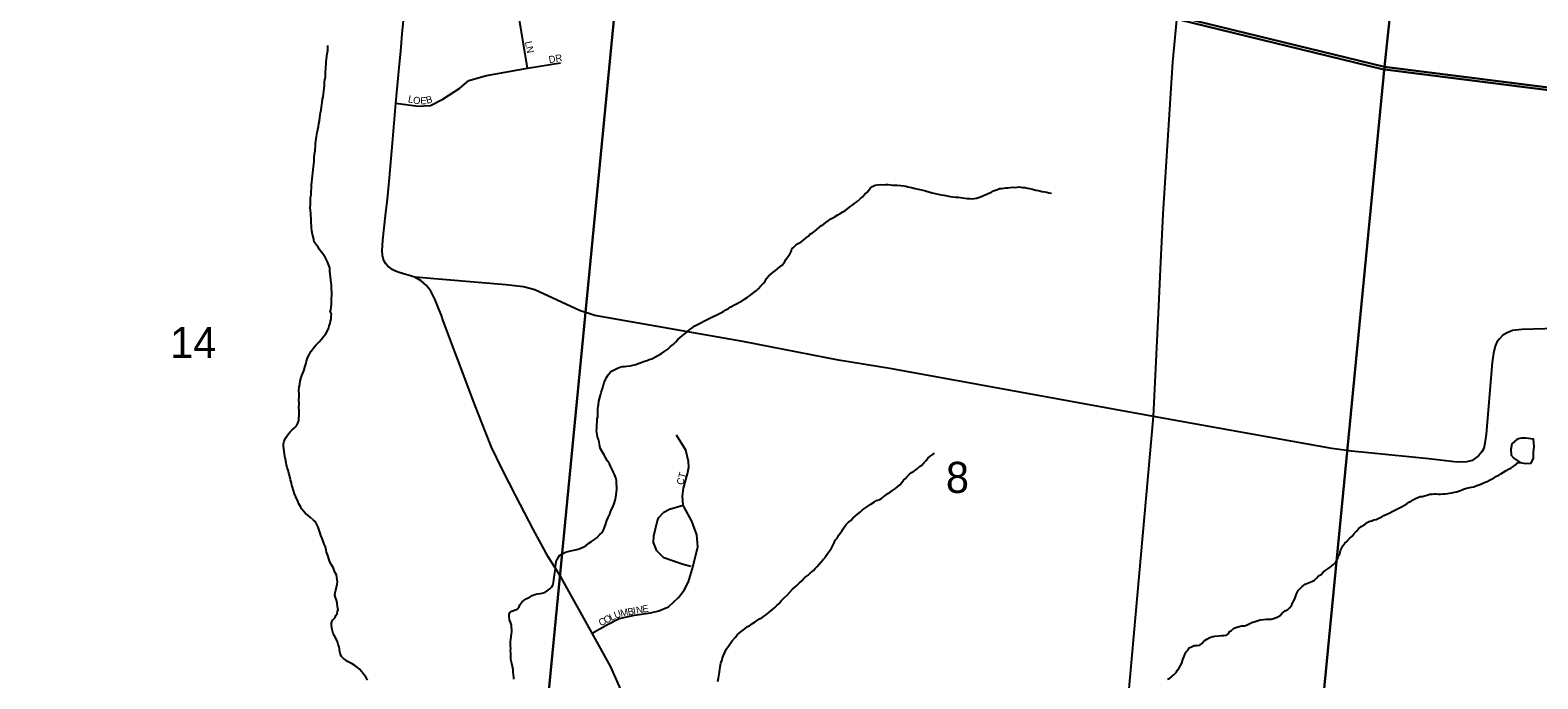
# Model space of a CAD drawing. Extents: x 0 to 1064, y 0 to 440.
# Drawn here: x 203.09 to 235.6, y 278.69 to 292.66 of the extents above; entities that cross this region are included whole.
import ezdxf

# ---------------------------------------------------------------- set-up
doc = ezdxf.new("R2010")
doc.units = 0
for name, color, linetype in [('GM_X_County_Road', 7, 'Continuous'), ('GM_X_Minor_Lake', 7, 'Continuous'), ('GM_X_Minor_River', 7, 'Continuous'), ('GM_X_Section', 7, 'Continuous'), ('GM_X_Section_Text', 7, 'Continuous'), ('GM_X_State_Route', 7, 'Continuous'), ('GM_X_Township', 7, 'Continuous'), ('GM_X_Township_Road', 7, 'Continuous'), ('GM_X_Township_Subdivision', 7, 'Continuous'), ('GM_X_Township_Subdivision_Text', 7, 'Continuous')]:
    doc.layers.add(name, color=color, linetype=linetype)

msp = doc.modelspace()

# ---------------------------------------------------------------- linework, layer by layer
at = {"layer": 'GM_X_County_Road'}
msp.add_lwpolyline([(227.217, 256.331), (227.021, 256.544), (226.463, 257.231), (226.198, 257.65), (225.438, 259.12), (225.221, 259.508), (225.122, 259.711), (225.097, 259.973), (225.685, 266.061), (225.937, 268.726), (226.312, 273.171), (227.313, 284.338), (227.421, 286.562), (227.469, 287.662), (227.522, 288.708), (227.683, 291.298), (227.726, 291.973), (227.812, 292.884)], dxfattribs=at)
at = {"layer": 'GM_X_Minor_Lake'}
for points in [[(235.24, 283.872), (235.154, 283.849), (235.042, 283.749), (235.015, 283.628), (235.024, 283.506), (235.083, 283.437), (235.221, 283.349)], [(235.221, 283.349), (235.33, 283.328), (235.458, 283.331), (235.503, 283.439), (235.506, 283.567), (235.522, 283.694), (235.507, 283.853), (235.337, 283.869), (235.24, 283.872)]]:
    msp.add_lwpolyline(points, dxfattribs=at)
at = {"layer": 'GM_X_Minor_River'}
for points in [[(209.589, 286.828), (209.591, 286.876), (209.594, 286.955), (209.595, 287.01), (209.592, 287.089), (209.588, 287.162), (209.578, 287.235), (209.574, 287.278), (209.564, 287.357), (209.559, 287.399), (209.556, 287.478), (209.552, 287.539), (209.524, 287.613), (209.502, 287.674), (209.462, 287.755), (209.433, 287.798), (209.404, 287.841), (209.368, 287.885), (209.328, 287.935), (209.299, 287.984), (209.264, 288.028), (209.217, 288.102), (209.207, 288.145), (209.191, 288.218), (209.18, 288.261), (209.164, 288.34), (209.161, 288.413), (209.156, 288.456), (209.152, 288.511), (209.147, 288.56), (209.149, 288.614), (209.145, 288.669), (209.14, 288.718), (209.136, 288.778), (209.132, 288.839), (209.134, 288.906), (209.136, 288.954), (209.137, 289.003), (209.139, 289.058), (209.147, 289.118), (209.15, 289.185), (209.158, 289.257), (209.16, 289.324), (209.162, 289.391), (209.171, 289.457), (209.179, 289.518), (209.187, 289.59), (209.19, 289.663), (209.198, 289.717), (209.206, 289.778), (209.214, 289.838), (209.216, 289.917), (209.225, 289.996), (209.233, 290.062), (209.235, 290.105), (209.242, 290.147), (209.245, 290.22), (209.252, 290.268), (209.268, 290.371), (209.283, 290.455), (209.297, 290.522), (209.306, 290.588), (209.314, 290.649), (209.328, 290.703), (209.336, 290.782), (209.344, 290.842), (209.352, 290.884), (209.366, 290.945), (209.374, 291.011), (209.382, 291.053), (209.39, 291.114), (209.398, 291.174), (209.406, 291.223), (209.414, 291.289), (209.422, 291.35), (209.43, 291.41), (209.438, 291.464), (209.441, 291.543), (209.448, 291.598), (209.456, 291.64), (209.457, 291.682), (209.459, 291.731), (209.461, 291.779), (209.468, 291.822), (209.47, 291.87), (209.472, 291.931), (209.473, 291.979), (209.481, 292.04), (209.49, 292.106), (209.497, 292.155), (209.506, 292.227), (209.508, 292.282), (209.509, 292.336)], [(219.515, 287.948), (219.559, 287.989), (219.602, 288.03), (219.652, 288.065), (219.708, 288.094), (219.771, 288.147), (219.821, 288.188), (219.871, 288.223), (219.902, 288.264), (219.958, 288.299), (220.002, 288.328), (220.058, 288.375), (220.108, 288.416), (220.152, 288.457), (220.202, 288.485), (220.246, 288.521), (220.296, 288.555), (220.352, 288.596), (220.395, 288.619), (220.445, 288.648), (220.507, 288.682), (220.557, 288.711), (220.613, 288.746), (220.675, 288.787), (220.725, 288.821), (220.787, 288.868), (220.831, 288.897), (220.874, 288.932), (220.918, 288.967), (220.987, 289.026), (221.037, 289.073), (221.088, 289.126), (221.132, 289.167), (221.176, 289.214), (221.208, 289.262), (221.252, 289.297), (221.308, 289.326), (221.362, 289.33), (221.417, 289.334), (221.49, 289.332), (221.533, 289.337), (221.594, 289.335), (221.642, 289.327), (221.685, 289.326), (221.74, 289.324), (221.788, 289.323), (221.861, 289.315), (221.928, 289.306), (221.97, 289.299), (222.012, 289.286), (222.097, 289.271), (222.176, 289.25), (222.236, 289.236), (222.309, 289.222), (222.393, 289.201), (222.466, 289.181), (222.538, 289.16), (222.604, 289.14), (222.671, 289.126), (222.732, 289.118), (222.792, 289.104), (222.865, 289.095), (222.925, 289.081), (222.986, 289.073), (223.046, 289.065), (223.101, 289.064), (223.15, 289.056), (223.192, 289.049), (223.247, 289.041), (223.295, 289.034), (223.35, 289.032), (223.404, 289.03), (223.447, 289.035), (223.496, 289.046), (223.558, 289.062), (223.619, 289.084), (223.663, 289.107), (223.718, 289.13), (223.762, 289.153), (223.817, 289.175), (223.861, 289.198), (223.904, 289.215), (223.947, 289.232), (223.99, 289.249), (224.039, 289.253), (224.125, 289.269), (224.173, 289.267), (224.222, 289.272), (224.265, 289.277), (224.326, 289.275), (224.375, 289.279), (224.424, 289.284), (224.484, 289.276), (224.539, 289.274), (224.593, 289.261), (224.636, 289.253), (224.702, 289.239), (224.774, 289.213), (224.823, 289.205), (224.865, 289.198), (224.908, 289.19)], [(224.908, 289.19), (224.968, 289.182), (225.011, 289.175), (225.053, 289.161), (225.113, 289.147)], [(215.374, 283.693), (215.369, 283.742), (215.358, 283.784), (215.348, 283.839), (215.326, 283.901), (215.315, 283.95), (215.31, 283.992), (215.3, 284.035), (215.313, 284.083), (215.31, 284.162), (215.318, 284.217), (215.32, 284.29), (215.328, 284.332), (215.33, 284.392), (215.331, 284.435), (215.334, 284.508), (215.341, 284.55), (215.342, 284.592), (215.351, 284.665), (215.365, 284.719), (215.386, 284.797), (215.406, 284.858), (215.433, 284.942), (215.454, 285.014), (215.468, 285.068), (215.494, 285.134), (215.52, 285.182), (215.552, 285.235), (215.597, 285.289), (215.641, 285.324), (215.709, 285.358), (215.752, 285.381), (215.807, 285.398), (215.857, 285.414), (215.906, 285.419), (215.954, 285.423), (216.028, 285.433), (216.083, 285.444), (216.15, 285.46), (216.2, 285.483), (216.262, 285.505), (216.317, 285.521), (216.397, 285.543), (216.44, 285.566), (216.496, 285.583), (216.576, 285.623), (216.638, 285.657), (216.706, 285.698), (216.775, 285.744), (216.837, 285.791), (216.9, 285.843), (216.956, 285.89), (217.007, 285.943), (217.057, 285.996), (217.107, 286.037), (217.157, 286.084), (217.214, 286.125), (217.258, 286.166), (217.314, 286.213), (217.358, 286.242), (217.42, 286.289), (217.482, 286.317), (217.538, 286.346), (217.618, 286.392), (217.686, 286.426), (217.748, 286.455), (217.804, 286.489), (217.884, 286.523), (217.928, 286.546), (217.983, 286.575), (218.046, 286.609), (218.089, 286.638), (218.145, 286.667), (218.201, 286.702), (218.263, 286.736), (218.319, 286.765), (218.387, 286.799), (218.443, 286.834), (218.492, 286.869), (218.548, 286.903), (218.63, 286.962), (218.698, 287.008), (218.754, 287.055), (218.792, 287.096), (218.849, 287.155), (218.906, 287.214), (218.938, 287.256), (218.97, 287.309), (219.014, 287.363), (219.058, 287.404), (219.108, 287.439), (219.164, 287.485), (219.208, 287.521), (219.252, 287.562), (219.308, 287.596), (219.353, 287.662), (219.392, 287.727), (219.424, 287.775), (219.468, 287.834), (219.507, 287.906), (219.515, 287.948)], [(209.631, 281.072), (209.59, 281.14), (209.556, 281.207), (209.534, 281.269), (209.512, 281.342), (209.484, 281.416), (209.473, 281.459), (209.457, 281.526), (209.428, 281.588), (209.406, 281.655), (209.384, 281.711), (209.361, 281.772), (209.345, 281.821), (209.328, 281.864), (209.317, 281.907), (209.3, 281.95), (209.272, 282.011), (209.243, 282.067), (209.202, 282.105), (209.137, 282.161), (209.078, 282.212), (209.03, 282.25), (208.983, 282.3), (208.948, 282.343), (208.925, 282.386), (208.885, 282.454), (208.862, 282.516), (208.823, 282.608), (208.794, 282.67), (208.772, 282.743), (208.751, 282.817), (208.734, 282.86), (208.723, 282.903), (208.707, 282.97), (208.691, 283.043), (208.669, 283.117), (208.653, 283.184), (208.636, 283.233), (208.62, 283.3), (208.61, 283.343), (208.594, 283.417), (208.584, 283.478), (208.573, 283.532), (208.569, 283.587), (208.559, 283.648), (208.554, 283.697), (208.556, 283.746), (208.57, 283.806), (208.597, 283.872), (208.622, 283.913), (208.661, 283.967), (208.699, 284.008), (208.743, 284.049), (208.786, 284.084), (208.837, 284.137), (208.863, 284.191), (208.883, 284.251), (208.885, 284.3), (208.893, 284.354), (208.888, 284.403), (208.891, 284.476), (208.886, 284.531), (208.889, 284.609), (208.886, 284.707), (208.888, 284.755), (208.89, 284.822), (208.886, 284.895), (208.889, 284.968), (208.903, 285.034), (208.911, 285.1), (208.932, 285.179), (208.952, 285.221), (208.972, 285.269), (208.992, 285.323), (209.005, 285.371), (209.019, 285.425), (209.04, 285.485), (209.053, 285.527), (209.074, 285.599), (209.106, 285.665), (209.145, 285.737), (209.171, 285.778), (209.215, 285.832), (209.26, 285.879), (209.323, 285.944), (209.373, 286.003), (209.424, 286.068), (209.469, 286.121), (209.501, 286.181), (209.528, 286.247), (209.535, 286.295), (209.561, 286.343), (209.569, 286.391), (209.583, 286.446), (209.584, 286.488), (209.592, 286.542), (209.563, 286.586), (209.571, 286.64), (209.579, 286.695), (209.587, 286.761), (209.589, 286.828)], [(213.488, 278.949), (213.478, 279.016), (213.461, 279.071), (213.457, 279.114), (213.458, 279.156), (213.453, 279.199), (213.455, 279.248), (213.45, 279.29), (213.452, 279.345), (213.447, 279.388), (213.449, 279.442), (213.451, 279.485), (213.452, 279.539), (213.46, 279.587), (213.468, 279.654), (213.476, 279.696), (213.478, 279.751), (213.473, 279.8), (213.469, 279.842), (213.446, 279.904), (213.43, 279.959), (213.42, 280.026), (213.421, 280.074), (213.435, 280.116), (213.479, 280.145), (213.534, 280.162), (213.589, 280.184), (213.634, 280.238), (213.653, 280.28), (213.692, 280.339), (213.742, 280.38), (213.786, 280.409), (213.829, 280.432), (213.872, 280.455), (213.916, 280.478), (213.971, 280.501), (214.033, 280.517), (214.088, 280.521), (214.131, 280.532), (214.186, 280.549), (214.242, 280.583), (214.298, 280.624), (214.336, 280.665), (214.362, 280.707), (214.376, 280.761), (214.384, 280.822), (214.391, 280.87), (214.399, 280.924), (214.407, 280.967), (214.408, 281.015), (214.416, 281.07), (214.418, 281.112), (214.425, 281.16), (214.44, 281.239), (214.466, 281.287), (214.504, 281.34), (214.573, 281.386), (214.635, 281.415), (214.684, 281.426), (214.776, 281.447), (214.849, 281.463), (214.905, 281.479), (214.966, 281.502), (215.028, 281.53), (215.078, 281.559), (215.14, 281.606), (215.196, 281.647), (215.259, 281.687), (215.315, 281.734), (215.372, 281.793), (215.422, 281.84), (215.454, 281.887), (215.474, 281.948), (215.501, 282.026), (215.528, 282.098), (215.555, 282.164), (215.587, 282.235), (215.614, 282.307), (215.647, 282.373), (215.673, 282.439), (215.687, 282.487), (215.714, 282.559), (215.721, 282.602), (215.729, 282.65), (215.737, 282.71), (215.739, 282.777), (215.741, 282.826), (215.737, 282.886), (215.733, 282.959), (215.717, 283.015), (215.689, 283.088), (215.672, 283.131), (215.643, 283.199), (215.615, 283.254), (215.58, 283.316), (215.534, 283.391), (215.5, 283.452), (215.465, 283.514), (215.43, 283.57), (215.39, 283.638), (215.374, 283.693)], [(221.295, 282.496), (221.339, 282.525), (221.388, 282.542), (221.444, 282.571), (221.5, 282.611), (221.543, 282.64), (221.587, 282.676), (221.637, 282.704), (221.706, 282.757), (221.749, 282.786), (221.799, 282.827), (221.843, 282.862), (221.887, 282.915), (221.925, 282.963), (221.963, 283.004), (222.001, 283.045), (222.051, 283.092), (222.095, 283.133), (222.139, 283.156), (222.182, 283.179), (222.226, 283.214), (222.27, 283.262), (222.314, 283.291), (222.364, 283.35), (222.408, 283.391), (222.447, 283.438), (222.49, 283.473), (222.534, 283.508), (222.59, 283.549)], [(231.731, 281.919), (231.793, 281.966), (231.868, 282.012), (231.918, 282.053), (231.979, 282.082), (232.022, 282.092), (232.066, 282.109), (232.115, 282.12), (232.158, 282.143), (232.232, 282.177), (232.276, 282.206), (232.344, 282.234), (232.406, 282.263), (232.474, 282.297), (232.542, 282.337), (232.616, 282.372), (232.66, 282.395), (232.709, 282.423), (232.771, 282.458), (232.821, 282.493), (232.865, 282.516), (232.908, 282.545), (232.964, 282.573), (233.013, 282.59), (233.063, 282.613), (233.111, 282.617), (233.154, 282.628), (233.216, 282.644), (233.265, 282.661), (233.32, 282.666), (233.363, 282.67), (233.405, 282.669), (233.46, 282.667), (233.503, 282.666), (233.552, 282.671), (233.6, 282.675), (233.655, 282.68), (233.698, 282.684), (233.747, 282.695), (233.802, 282.705), (233.845, 282.716), (233.888, 282.727), (233.932, 282.744), (233.993, 282.772), (234.036, 282.783), (234.098, 282.799), (234.171, 282.815), (234.22, 282.826), (234.282, 282.848), (234.325, 282.865), (234.368, 282.882), (234.412, 282.905), (234.461, 282.922), (234.504, 282.939), (234.56, 282.967), (234.616, 282.996), (234.659, 283.019), (234.709, 283.054), (234.758, 283.076), (234.802, 283.105), (234.858, 283.14), (234.914, 283.175), (234.97, 283.204), (235.019, 283.226), (235.063, 283.255), (235.119, 283.296), (235.157, 283.337), (235.221, 283.349)], [(217.922, 278.63), (217.93, 278.697), (217.938, 278.745), (217.945, 278.787), (217.953, 278.83), (217.961, 278.884), (217.969, 278.944), (217.984, 279.023), (218.01, 279.095), (218.018, 279.137), (218.038, 279.185), (218.07, 279.251), (218.103, 279.329), (218.161, 279.412), (218.225, 279.501), (218.294, 279.578), (218.345, 279.637), (218.389, 279.678), (218.445, 279.719), (218.501, 279.76), (218.558, 279.813), (218.601, 279.829), (218.669, 279.876), (218.725, 279.911), (218.769, 279.94), (218.819, 279.975), (218.869, 280.003), (218.925, 280.044), (218.968, 280.073), (219.018, 280.114), (219.094, 280.179), (219.137, 280.214), (219.188, 280.267), (219.238, 280.308), (219.282, 280.367), (219.352, 280.432), (219.414, 280.49), (219.471, 280.555), (219.528, 280.62), (219.578, 280.661), (219.628, 280.702), (219.673, 280.749), (219.729, 280.796), (219.767, 280.838), (219.805, 280.879), (219.867, 280.92), (219.911, 280.961), (219.98, 281.019), (220.018, 281.061), (220.062, 281.108), (220.106, 281.155), (220.15, 281.208), (220.195, 281.262), (220.239, 281.309), (220.265, 281.35), (220.29, 281.392), (220.335, 281.451), (220.373, 281.499), (220.426, 281.613), (220.452, 281.673), (220.49, 281.714), (220.522, 281.774), (220.554, 281.821), (220.592, 281.869), (220.624, 281.916), (220.65, 281.964), (220.688, 282.011), (220.739, 282.064), (220.783, 282.099), (220.827, 282.147), (220.877, 282.188), (220.933, 282.234), (220.996, 282.287), (221.04, 282.328), (221.083, 282.357), (221.146, 282.398), (221.22, 282.45), (221.295, 282.496)], [(227.611, 278.677), (227.66, 278.694), (227.71, 278.735), (227.76, 278.776), (227.804, 278.823), (227.83, 278.871), (227.869, 278.924), (227.895, 278.972), (227.921, 279.026), (227.942, 279.104), (227.968, 279.152), (227.988, 279.206), (228.014, 279.266), (228.058, 279.313), (228.084, 279.355), (228.133, 279.377), (228.189, 279.4), (228.25, 279.404), (228.311, 279.414), (228.355, 279.443), (228.405, 279.503), (228.461, 279.537), (228.53, 279.578), (228.591, 279.594), (228.634, 279.605), (228.714, 279.614), (228.775, 279.619), (228.829, 279.617), (228.884, 279.627), (228.928, 279.656), (228.954, 279.704), (228.997, 279.727), (229.035, 279.768), (229.085, 279.791), (229.158, 279.813), (229.214, 279.824), (229.275, 279.828), (229.318, 279.845), (229.373, 279.867), (229.435, 279.896), (229.503, 279.918), (229.546, 279.935), (229.614, 279.957), (229.687, 279.961), (229.748, 279.971), (229.803, 279.969), (229.852, 279.974), (229.901, 279.985), (229.944, 280.001), (229.993, 280.018), (230.043, 280.053), (230.081, 280.094), (230.15, 280.147), (230.206, 280.176), (230.243, 280.217), (230.294, 280.27), (230.302, 280.318), (230.333, 280.36), (230.359, 280.408), (230.38, 280.474), (230.4, 280.528), (230.432, 280.587), (230.508, 280.67), (230.583, 280.728), (230.651, 280.751), (230.725, 280.785), (230.781, 280.813), (230.837, 280.86), (230.869, 280.902), (230.925, 280.936), (230.969, 280.984), (231.025, 281.03), (231.069, 281.059), (231.125, 281.094), (231.187, 281.141), (231.238, 281.188), (231.277, 281.266), (231.303, 281.338), (231.329, 281.379), (231.344, 281.452), (231.363, 281.494), (231.396, 281.553), (231.44, 281.607), (231.484, 281.648), (231.535, 281.707), (231.597, 281.76), (231.642, 281.819), (231.686, 281.866), (231.731, 281.919)], [(210.367, 278.657), (210.338, 278.712), (210.286, 278.781), (210.245, 278.837), (210.192, 278.893), (210.145, 278.937), (210.091, 278.975), (210.031, 279.007), (209.989, 279.033), (209.935, 279.059), (209.888, 279.097), (209.846, 279.122), (209.805, 279.166), (209.777, 279.228), (209.766, 279.27), (209.761, 279.319), (209.751, 279.374), (209.734, 279.423), (209.718, 279.484), (209.684, 279.558), (209.655, 279.614), (209.627, 279.663), (209.61, 279.718), (209.594, 279.774), (209.59, 279.847), (209.592, 279.895), (209.612, 279.949), (209.669, 280.008), (209.682, 280.05), (209.708, 280.092), (209.721, 280.134), (209.729, 280.182), (209.719, 280.237), (209.709, 280.316), (209.693, 280.378), (209.677, 280.439), (209.66, 280.488), (209.668, 280.536), (209.682, 280.596), (209.696, 280.657), (209.71, 280.723), (209.718, 280.765), (209.714, 280.826), (209.703, 280.869), (209.693, 280.924), (209.664, 280.986), (209.647, 281.029), (209.631, 281.072)], [(213.521, 278.681), (213.517, 278.73), (213.512, 278.772), (213.508, 278.827), (213.504, 278.882), (213.488, 278.949)]]:
    msp.add_lwpolyline(points, dxfattribs=at)
at = {"layer": 'GM_X_Section'}
for points in [[(234.053, 308.422), (232.294, 291.87), (215.966, 295.854), (217.525, 311.775), (219.433, 311.739)], [(234.053, 308.422), (250.392, 306.037), (248.821, 289.79), (232.294, 291.87)], [(215.966, 295.854), (214.149, 277.17), (197.538, 278.526), (198.919, 293.248)], [(232.294, 291.87), (230.695, 275.436), (214.149, 277.17), (215.966, 295.854)], [(248.821, 289.79), (247.278, 273.713), (230.695, 275.436), (232.294, 291.87)]]:
    msp.add_lwpolyline(points, close=True, dxfattribs=at)
at = {"layer": 'GM_X_State_Route'}
msp.add_lwpolyline([(215.877, 278.344), (215.61, 278.945), (215.208, 279.667), (214.53, 280.881), (214.26, 281.311), (213.94, 281.908), (213.561, 282.628), (213.258, 283.218), (213.038, 283.679), (212.917, 283.986), (212.682, 284.586), (212.428, 285.257), (212.357, 285.448), (212.25, 285.73), (212.052, 286.25), (211.997, 286.4), (211.957, 286.511), (211.881, 286.706), (211.839, 286.813), (211.814, 286.868), (211.781, 286.941), (211.751, 286.998), (211.72, 287.05), (211.675, 287.112), (211.638, 287.158), (211.521, 287.263), (211.389, 287.338), (211.05, 287.444), (210.97, 287.471), (210.897, 287.508), (210.852, 287.538), (210.805, 287.579), (210.762, 287.628), (210.727, 287.684), (210.706, 287.742), (210.688, 287.81), (210.684, 287.915), (210.686, 288.014), (210.697, 288.136), (210.752, 288.669), (210.793, 289.023), (210.839, 289.483), (210.905, 290.23), (210.978, 291.09), (211.056, 291.933), (211.082, 292.211), (211.115, 292.585), (211.141, 292.874)], dxfattribs=at)
at = {"layer": 'GM_X_Township'}
for points in [[(294.912, 286.455), (282.136, 287.779), (265.78, 288.451), (265.672, 288.456), (263.063, 288.654), (248.776, 289.74), (232.24, 291.824), (227.881, 292.885)], [(227.881, 292.885), (232.24, 291.824), (248.776, 289.74), (263.063, 288.654), (265.672, 288.456), (265.78, 288.451), (282.136, 287.779), (294.912, 286.455)]]:
    msp.add_lwpolyline(points, dxfattribs=at)
at = {"layer": 'GM_X_Township_Road'}
msp.add_lwpolyline([(236.732, 286.255), (235.257, 286.215), (235.054, 286.19), (234.941, 286.142), (234.847, 286.092), (234.775, 286.012), (234.718, 285.942), (234.677, 285.856), (234.64, 285.703), (234.618, 285.504), (234.484, 283.957), (234.458, 283.764), (234.432, 283.652), (234.392, 283.574), (234.32, 283.492), (234.184, 283.39), (234.069, 283.36), (233.86, 283.355), (233.25, 283.426), (231.949, 283.552), (231.584, 283.591), (231.155, 283.652), (227.313, 284.338), (221.673, 285.362), (220.522, 285.554), (218.459, 285.957), (215.266, 286.513), (214.939, 286.625), (213.97, 287.069), (213.729, 287.131), (213.344, 287.175), (211.389, 287.338)], dxfattribs=at)
at = {"layer": 'GM_X_Township_Subdivision'}
for points in [[(213.812, 291.846), (213.402, 294.32)], [(210.978, 291.09), (211.459, 291.026), (211.72, 291.04), (211.989, 291.175), (212.356, 291.415), (212.547, 291.578), (212.929, 291.684), (213.812, 291.846), (214.526, 291.959)], [(215.208, 279.667), (215.538, 279.857), (215.793, 279.985), (216.12, 280.057), (216.47, 280.104), (216.65, 280.148), (216.853, 280.24), (217.073, 280.435), (217.19, 280.599), (217.285, 280.776), (217.379, 281.092), (217.49, 281.53), (217.466, 281.785), (217.355, 282.08), (217.195, 282.385), (217.171, 282.431), (217.155, 282.622), (217.179, 282.797), (217.267, 283.1), (217.294, 283.249), (217.287, 283.371), (217.227, 283.61), (217.028, 283.937)], [(217.339, 281.103), (217.169, 281.149), (216.755, 281.295), (216.602, 281.441), (216.535, 281.625), (216.539, 281.768), (216.612, 282.071), (216.64, 282.151), (216.755, 282.28), (216.873, 282.342), (217.171, 282.431)]]:
    msp.add_lwpolyline(points, dxfattribs=at)

# ---------------------------------------------------------------- texts
at = {"layer": 'GM_X_Section_Text'}
for s, height, p in [('14', 0.6697, (206.11, 285.596)), ('8', 0.67, (222.836, 282.691))]:
    msp.add_text(s, height=height, rotation=0, dxfattribs=at).set_placement(p)
at = {"layer": 'GM_X_Township_Subdivision_Text'}
for s, height, rotation, p in [('LN', 0.1515, 281.8817, (213.758, 292.409)), ('DR', 0.1515, 9.4584, (214.285, 291.951)), ('L', 0.152, 348.7276, (211.23, 291.111)), ('O', 0.152, 349.5571, (211.337, 291.089)), ('E', 0.152, 2.9917, (211.507, 291.063)), ('B', 0.152, 14.6932, (211.647, 291.073)), ('CT', 0.1515, 74.4709, (217.169, 282.851)), ('B', 0.152, 10.105, (215.987, 280.052)), ('I', 0.152, 10.0994, (216.105, 280.074)), ('N', 0.152, 10.1183, (216.171, 280.085)), ('E', 0.152, 10.1045, (216.302, 280.109)), ('C', 0.152, 27.184, (215.396, 279.815)), ('O', 0.152, 27.1711, (215.503, 279.87)), ('L', 0.152, 27.1759, (215.622, 279.931)), ('U', 0.152, 20.799, (215.713, 279.978)), ('M', 0.152, 10.642, (215.83, 280.023))]:
    msp.add_text(s, height=height, rotation=rotation, dxfattribs=at).set_placement(p)

doc.saveas('drawing.dxf')
